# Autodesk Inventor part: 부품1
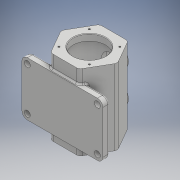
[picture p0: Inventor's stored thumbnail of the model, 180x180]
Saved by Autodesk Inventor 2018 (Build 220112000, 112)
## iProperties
Created: 2021-06
Part Number: 부품1
Material: Generic
Document SubType Name: Modeling
Designer: 1class 18
Density: 1 g/cm^3
Appearance: Default
Author: 1class 18
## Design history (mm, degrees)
sketch "스케치1"
  geometry: L1 (-26.183, 45.505)-(26.317, 45.428); L2 (26.317, 45.428)-(52.5, -0.077); L3 (52.5, -0.077)-(26.183, -45.505); L4 (26.183, -45.505)-(-26.317, -45.428); L5 (-26.317, -45.428)-(-52.5, 0.077); L6 (-52.5, 0.077)-(-26.183, 45.505); 2 further points
  constraints: 12 end point, 13 other
  dimensions: "d1" = 90.93267 distance between parallel lines of L2 L5; "d2" = 45.46633 distance from line of point (0, 0) L2; "d3" = 45.46633 distance from line of point (0, 0) L3
extrude "돌출1" new body sketch "스케치1" stored distance "d4" = 140; taper "d5" = 0 deg
sketch "스케치2"
  geometry: L1 (0.077, 70)-(0.077, -70) reference; L2 (0.077, 70)-(30.077, 70); L3 (30.077, 70)-(30.077, 58); L4 (30.077, 58)-(0.077, 58); L5 (0.077, 58)-(0.077, 70); L6 (0.077, 58)-(37.577, 58); L7 (37.577, 58)-(37.577, -58); L8 (37.577, -58)-(0.077, -58); L9 (0.077, -58)-(0.077, 58); L10 (0.077, -70)-(45.505, -70) reference; L11 (0.077, -58)-(30.077, -58); L12 (30.077, -58)-(30.077, -70); L13 (30.077, -70)-(0.077, -70); L14 (0.077, -70)-(0.077, -58); 1 further point
  constraints: 24 end point, 6 parallel, 3 horizontal, 3 perpendicular, 2 point on line
  dimensions: "d6" = 12 distance of L2.end L3.end; "d7" = 12 distance of L11.end L12.end; "d8" = 60 diameter of L3 L1; "d9" = 75 diameter of L7 L1
revolve "회전1" sketch "스케치2" stored, may be unused: angle "d10" = 90 deg
sketch "스케치3" dims "d11" = 80
  geometry: 3 further points
  constraints: 1 coincident, 1 vertical alignment, 2 other
hole "구멍1" sketch "스케치3" at (0, 40) diameter "d12" = 3.242; stored, may be unused: countersink angle "d16" = 90 deg, drill point angle "d18" = 118 deg; dims "d13" = 8, "d14" = 4, "d15" = 2, "d17" = 10
node "작업 평면1"
sketch "스케치4"
  geometry: L1 (-26.317, 70)-(26.183, 70) reference; C1 r 20 at (0, 30); 1 further point
  constraints: 1 centre point
  dimensions: "d23" = 40 distance from line of L1 C1.centre; "d25" = 40 diameter of C1; "d27" = 30 distance of point (0, 0) C1.centre
extrude "돌출2" join sketch "스케치4" stored distance "d28" = 8; taper "d29" = 0 deg
hole "구멍2" diameter "d32" = 30; stored, may be unused: countersink angle "d36" = 90 deg, drill point angle "d38" = 0 deg; dims "d30" = 10, "d31" = 10, "d33" = 8, "d34" = 4, "d35" = 2, "d37" = 8
hole "구멍3" diameter "d41" = 25; stored, may be unused: countersink angle "d45" = 90 deg, drill point angle "d47" = 0 deg; dims "d39" = 10, "d40" = 10, "d42" = 8, "d43" = 4, "d44" = 2, "d46" = 8
node "작업 평면2"
sketch "스케치5"
  geometry: L1 (26.183, 70)-(52.5, 70) reference; L2 (75, 45)-(-75, 45); L3 (-75, 45)-(-75, -55); L4 (-75, -55)-(75, -55); L5 (75, -55)-(75, 45); C1 r 12.5 at (0, 30) reference; 1 further point
  constraints: 8 end point, 2 parallel, 1 horizontal, 1 perpendicular
  dimensions: "d52" = 150 distance of L4.end L3.end; "d53" = 100 distance of L3.end L2.end; "d54" = 25 distance between parallel lines of L1 L2; "d55" = 75 distance from line of L3 point (0, 0)
extrude "돌출3" join sketch "스케치5" distance "d56" = 12; taper "d57" = 0 deg
fillet "모깎기1" dims "d58" = 10
hole "구멍4" diameter "d61" = 11; stored, may be unused: countersink angle "d65" = 90 deg, drill point angle "d67" = 0 deg; dims "d59" = 10, "d60" = 10, "d62" = 8, "d63" = 4, "d64" = 2, "d66" = 8
hole "구멍5" diameter "d73" = 11; stored, may be unused: countersink angle "d77" = 90 deg, drill point angle "d79" = 0 deg; dims "d71" = 10, "d72" = 10, "d74" = 8, "d75" = 4, "d76" = 2, "d78" = 8
fillet "모깎기2" dims "d83" = 8
chamfer "모따기1" distance "d84" = 1; stored, may be unused: second distance "d85" = 2, angle "d86" = 45 deg
fillet "모깎기3" dims "d87" = 5
fillet "모깎기4" dims "d88" = 3
sketch "스케치6"
  geometry: L1 (-65, -45)-(-32.326, -45) reference; L2 (-75, 45)-(-75, -35) reference; 2 further points
  constraints: 1 other
  dimensions: "d89" = 50 distance from line of L1 point (-61, 5); "d90" = 14 distance from line of L2 point (-61, 5)
feature "엠보싱1" sketch "스케치6" dims "d1" = 90.93267, "d2" = 45.46633, "d3" = 45.46633, "d6" = 12, "d7" = 12, "d8" = 60, "d9" = 75, "d91" = 0.5, "d92" = 0
sketch "스케치7" dims "d93" = 80
  geometry: L1 (0, 0)-(0, 70.159); L2 (0, 0)-(-46.367, 46.367); 2 further points
  constraints: 4 end point, 1 coincident, 1 point on line, 1 vertical, 3 other
  dimensions: "d101" = 45 deg angle of L2 L1
hole "구멍7" sketch "스케치7" at (-28.284, 28.284) diameter "d102" = 3.242; stored, may be unused: countersink angle "d106" = 90 deg, drill point angle "d108" = 118 deg; dims "d103" = 8, "d104" = 4, "d105" = 2, "d107" = 10
node "솔리드1"
pattern_circular "원형 패턴1" dims angle "d20" = 360 deg
mirror "미러1"
pattern_linear "직사각형 패턴1" dims "d70" = 130
pattern_linear "직사각형 패턴2" dims "d82" = 130
pattern_circular "원형 패턴2" dims angle "d110" = 360 deg
other parameters: "d22" = 52.5
